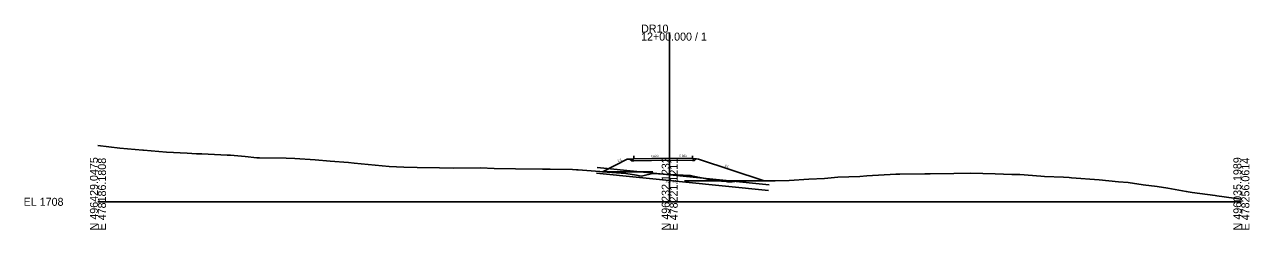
# Model space of a CAD drawing. Extents: x -26 to 403, y -10 to 2062.
# Drawn here: x -25.7 to 402.8, y 1990.3 to 2062.1 of the extents above; entities that cross this region are included whole.
import ezdxf

# ---------------------------------------------------------------- set-up
doc = ezdxf.new("R2010")
doc.units = 0
for name, color, linetype in [('Exist Cross Section Cell', 7, 'Continuous'), ('Exist XS Center Line Elevation Label', 7, 'Continuous'), ('Exist XS Ground Line', 7, 'Continuous'), ('Prop XS Dump Level', 7, 'Continuous'), ('Prop XS Earthwork Shape', 7, 'Continuous'), ('Prop XS EOT Tick Mark', 7, 'Continuous'), ('Prop XS Finish Grade', 7, 'Continuous'), ('Prop XS Finish Grade Earthwork', 7, 'Continuous'), ('Prop XS Finish Grade Pavement', 7, 'Continuous'), ('Prop XS Pvmt Edge Slope', 7, 'Continuous'), ('Prop XS SE Text', 7, 'Continuous'), ('Prop XS Shoulder Borrow Shape', 7, 'Continuous'), ('Prop XS Side Slope Text', 7, 'Continuous'), ('Prop XS Subgrade Earthwork', 7, 'Continuous'), ('Scratch_Level_5', 7, 'Continuous'), ('Scratch_Level_9', 7, 'Continuous')]:
    doc.layers.add(name, color=color, linetype=linetype)

msp = doc.modelspace()

# ---------------------------------------------------------------- linework, layer by layer
at = {"layer": 'Exist Cross Section Cell'}
for p, q in [((200, 2000), (200, 2059.23)), ((0, 2000), (200, 2000)), ((200, 2000), (400, 2000))]:
    msp.add_line(p, q, dxfattribs=at)
at = {"layer": 'Exist XS Ground Line'}
msp.add_lwpolyline([(0, 2019.74), (7.69, 2018.84), (15.65, 2018.12), (15.97, 2018.1), (23.98, 2017.39), (31.18, 2017.09), (34.46, 2016.83), (36.4, 2016.76), (45.23, 2016.39), (46.38, 2016.38), (51.46, 2015.83), (55.63, 2015.44), (56.53, 2015.43), (65.79, 2015.29), (68.88, 2015.13), (75.95, 2014.73), (81.23, 2014.24), (87.64, 2013.74), (89.65, 2013.59), (101.84, 2012.39), (107.02, 2012.17), (111.69, 2012.05), (119.53, 2011.88), (124.34, 2011.77), (133.85, 2011.88), (138.66, 2011.7), (146.12, 2011.51), (155.56, 2011.44), (158.25, 2011.39), (165.97, 2011.27), (167.37, 2011.24), (167.98, 2011.19), (184.71, 2009.91), (188.39, 2009.29), (189.99, 2009), (190.64, 2009.14), (194.03, 2009.92), (198.07, 2009.7), (200, 2009.6), (207.23, 2009.24), (210.44, 2008.57), (211.85, 2008.26), (213.23, 2007.98), (218.14, 2007.27), (219.8, 2007.15), (220.29, 2007.03), (221.89, 2007.03), (222.81, 2007.1), (224.7, 2007.35), (232.78, 2007.32), (235.79, 2007.33), (236.93, 2007.35), (241.77, 2007.49), (248.64, 2007.88), (254.12, 2008.22), (258.79, 2008.68), (266.47, 2008.92), (268.95, 2009.12), (279.11, 2009.66), (280.47, 2009.68), (289.27, 2009.83), (291.17, 2009.82), (299.43, 2009.93), (305.2, 2010.03), (309.59, 2009.87), (313.83, 2009.77), (319.74, 2009.62), (322.45, 2009.51), (329.9, 2008.96), (331.08, 2008.89), (337.72, 2008.58), (339.77, 2008.51), (340.56, 2008.45), (350.22, 2007.72), (356.96, 2007.03), (360.38, 2006.71), (365.59, 2005.94), (370.53, 2005.34), (374.22, 2004.8), (380.69, 2003.67), (382.84, 2003.29), (390.85, 2002.2), (391.47, 2002.08), (397.34, 2001.3), (400, 2000.94)], dxfattribs=at)
at = {"layer": 'Prop XS Dump Level'}
for p, q in [((187.5, 2015.06), (200, 2015.31)), ((200, 2015.31), (208.03, 2015.15))]:
    msp.add_line(p, q, dxfattribs=at)
at = {"layer": 'Prop XS Earthwork Shape'}
msp.add_lwpolyline([(208.03, 2014.48), (208.71, 2014.47), (209.29, 2015.05), (210.03, 2014.99), (233.03, 2007.32), (232.78, 2007.32), (224.7, 2007.35), (222.81, 2007.1), (221.89, 2007.03), (220.29, 2007.03), (219.8, 2007.15), (218.14, 2007.27), (213.23, 2007.98), (211.85, 2008.26), (210.44, 2008.57), (207.23, 2009.24), (200, 2009.6), (198.07, 2009.7), (194.03, 2009.92), (190.64, 2009.14), (189.99, 2009), (188.39, 2009.29), (184.71, 2009.91), (176.46, 2010.54), (185.17, 2014.9), (186.03, 2014.96), (186.71, 2014.38), (187.5, 2014.39), (200, 2014.64)], close=True, dxfattribs=at)
at = {"layer": 'Prop XS EOT Tick Mark'}
for p, q in [((187.5, 2015.06), (187.5, 2016.06)), ((208.03, 2015.15), (208.03, 2016.15))]:
    msp.add_line(p, q, dxfattribs=at)
at = {"layer": 'Prop XS Finish Grade'}
for p, q in [((187.5, 2015.06), (186.03, 2014.96)), ((208.03, 2015.15), (209.29, 2015.05))]:
    msp.add_line(p, q, dxfattribs=at)
at = {"layer": 'Prop XS Finish Grade Earthwork'}
for p, q in [((185.17, 2014.9), (176.46, 2010.54)), ((186.03, 2014.96), (185.17, 2014.9)), ((209.29, 2015.05), (210.03, 2014.99)), ((210.03, 2014.99), (233.03, 2007.32))]:
    msp.add_line(p, q, dxfattribs=at)
at = {"layer": 'Prop XS Finish Grade Pavement'}
for p, q in [((187.5, 2015.06), (200, 2015.31)), ((200, 2015.31), (208.03, 2015.15))]:
    msp.add_line(p, q, dxfattribs=at)
at = {"layer": 'Prop XS Pvmt Edge Slope'}
for p, q in [((187.5, 2015.06), (186.71, 2014.38)), ((208.03, 2015.15), (208.71, 2014.47))]:
    msp.add_line(p, q, dxfattribs=at)
at = {"layer": 'Prop XS Shoulder Borrow Shape'}
for points in [[(187.5, 2015.06), (186.03, 2014.96), (186.71, 2014.38)], [(208.03, 2015.15), (209.29, 2015.05), (208.71, 2014.47)]]:
    msp.add_lwpolyline(points, close=True, dxfattribs=at)
at = {"layer": 'Prop XS Subgrade Earthwork'}
for p, q in [((186.71, 2014.38), (186.03, 2014.96)), ((187.5, 2014.39), (186.71, 2014.38)), ((200, 2014.64), (187.5, 2014.39)), ((208.03, 2014.48), (200, 2014.64)), ((208.03, 2014.48), (208.71, 2014.47)), ((208.71, 2014.47), (209.29, 2015.05))]:
    msp.add_line(p, q, dxfattribs=at)
at = {"layer": 'Scratch_Level_5'}
msp.add_lwpolyline([(0, 2019.74), (7.69, 2018.84), (15.65, 2018.12), (15.97, 2018.1), (23.98, 2017.39), (31.18, 2017.09), (34.46, 2016.83), (36.4, 2016.76), (45.23, 2016.39), (46.38, 2016.38), (51.46, 2015.83), (55.63, 2015.44), (56.53, 2015.43), (65.79, 2015.29), (68.88, 2015.13), (75.95, 2014.73), (81.23, 2014.24), (87.64, 2013.74), (89.65, 2013.59), (101.84, 2012.39), (107.02, 2012.17), (111.69, 2012.05), (119.53, 2011.88), (124.34, 2011.77), (133.85, 2011.88), (138.66, 2011.7), (146.12, 2011.51), (155.56, 2011.44), (158.25, 2011.39), (165.97, 2011.27), (167.37, 2011.24), (167.98, 2011.19), (184.71, 2009.91), (188.39, 2009.29), (189.99, 2009), (190.64, 2009.14), (194.03, 2009.92), (198.07, 2009.7), (200, 2009.6), (207.23, 2009.24), (210.44, 2008.57), (211.85, 2008.26), (213.23, 2007.98), (218.14, 2007.27), (219.8, 2007.15), (220.29, 2007.03), (221.89, 2007.03), (222.81, 2007.1), (224.7, 2007.35), (232.78, 2007.32), (235.79, 2007.33), (236.93, 2007.35), (241.77, 2007.49), (248.64, 2007.88), (254.12, 2008.22), (258.79, 2008.68), (266.47, 2008.92), (268.95, 2009.12), (279.11, 2009.66), (280.47, 2009.68), (289.27, 2009.83), (291.17, 2009.82), (299.43, 2009.93), (305.2, 2010.03), (309.59, 2009.87), (313.83, 2009.77), (319.74, 2009.62), (322.45, 2009.51), (329.9, 2008.96), (331.08, 2008.89), (337.72, 2008.58), (339.77, 2008.51), (340.56, 2008.45), (350.22, 2007.72), (356.96, 2007.03), (360.38, 2006.71), (365.59, 2005.94), (370.53, 2005.34), (374.22, 2004.8), (380.69, 2003.67), (382.84, 2003.29), (390.85, 2002.2), (391.47, 2002.08), (397.34, 2001.3), (400, 2000.94)], dxfattribs=at)
at = {"layer": 'Scratch_Level_9'}
for p, q in [((174.43, 2010), (234.6, 2004)), ((174.63, 2011.99), (234.8, 2005.99)), ((176.46, 2010.54), (194.11, 2010.54)), ((205.2, 2007.35), (229.25, 2007.35))]:
    msp.add_line(p, q, dxfattribs=at)

# ---------------------------------------------------------------- texts
at = {"layer": 'Exist Cross Section Cell'}
for s, p in [('DR10', (190, 2059.23)), ('12+00.000 / 1', (190, 2056.43)), ('EL 1708', (-26, 1998.6))]:
    msp.add_text(s, height=2.8, dxfattribs=at).set_placement(p)
for s, p in [('N 496429.0475', (0, 1990)), ('E 478186.1808', (2.8, 1990)), ('N 496232.1232', (200, 1990)), ('E 478221.1211', (202.8, 1990)), ('N 496035.1989', (400, 1990)), ('E 478256.0614', (402.8, 1990))]:
    msp.add_text(s, height=2.8, rotation=90, dxfattribs=at).set_placement(p)
at = {"layer": 'Exist XS Center Line Elevation Label'}
msp.add_text('1717.60', height=0.75, dxfattribs=at).set_placement((198.47, 2006.85))
at = {"layer": 'Prop XS Dump Level'}
for p in [(185.17, 2014.86), (210.03, 2014.95)]:
    msp.add_text('Case1', height=0.04, dxfattribs=at).set_placement(p)
at = {"layer": 'Prop XS SE Text'}
for rotation, p in [(1.1458, (193.47, 2015.66)), (358.8542, (203.37, 2015.75))]:
    msp.add_text('0.020', height=0.75, rotation=rotation, dxfattribs=at).set_placement(p)
at = {"layer": 'Prop XS Side Slope Text'}
for s, rotation, p in [('2:1', 26.5651, (182.03, 2013.96)), ('3:1', 341.5651, (219.14, 2012.41))]:
    msp.add_text(s, height=0.75, rotation=rotation, dxfattribs=at).set_placement(p)

doc.saveas('drawing.dxf')
